(* Logix 5000 project; controller DNP3Outstation 1756-L62 rev 19.11; software revision 19.01; part 3 of 3 *)
(* tags used below, declared in another part *)
   DNP3TimeNeededMsg : MESSAGE;
   SetDNP3TimeNeeded : BOOL;
(* DNP3Outstation, continued *)

ROUTINE Services   (* ladder *)
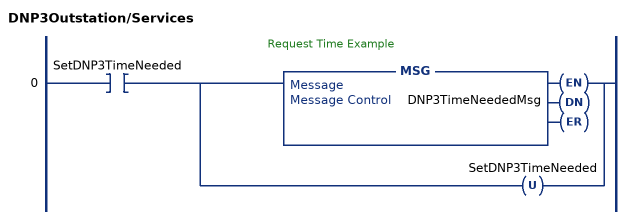
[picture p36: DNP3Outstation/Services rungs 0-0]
   // Request Time Example
   0: XIC(SetDNP3TimeNeeded)[MSG(DNP3TimeNeededMsg) ,OTU(SetDNP3TimeNeeded) ];
END_ROUTINE
END_PROGRAM
